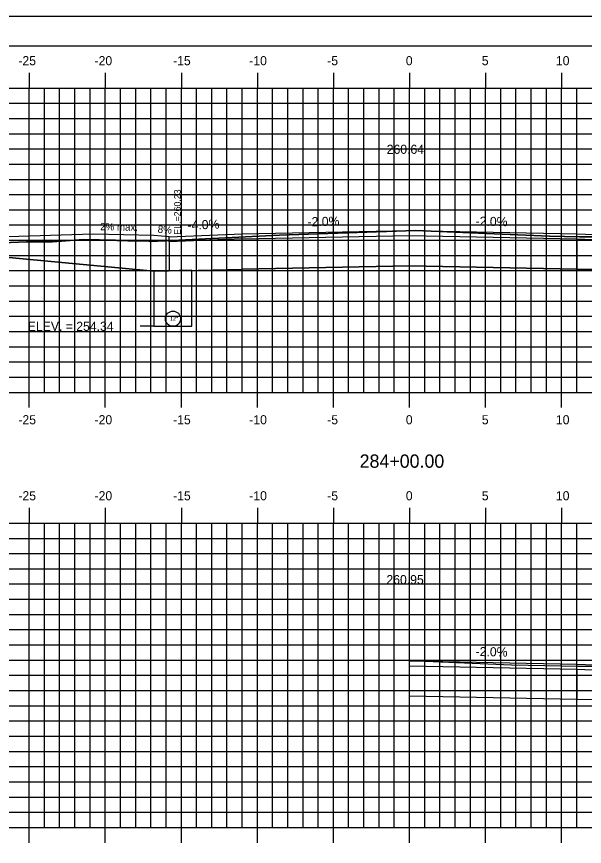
# Model space of a CAD drawing. Extents: x 856235 to 856405, y 366268 to 366378.
# Drawn here: x 856291.9 to 856329.3, y 366323.6 to 366378.2 of the extents above; entities that cross this region are included whole.
import ezdxf

# ---------------------------------------------------------------- set-up
doc = ezdxf.new("R2010")
doc.units = 0
for name, color, linetype in [('ANNOTATION', 7, 'Continuous'), ('BORDER', 7, 'Continuous'), ('D_Roadway_Centerline', 7, 'Continuous'), ('D_Roadway_Centerline_Text', 7, 'Continuous'), ('D_Roadway_Drive_Gravel_LT', 7, 'Continuous'), ('D_Roadway_Drive_SubGrade', 7, 'Continuous'), ('D_Roadway_Edge_Shoulder', 7, 'Continuous'), ('D_Roadway_SubGrade', 7, 'Continuous'), ('D_Text_Standard', 7, 'Continuous'), ('H_V ANNOTATION', 7, 'Continuous'), ('JUNK COM EXC', 7, 'Continuous'), ('junk strct exc', 7, 'Continuous'), ('MAJOR', 7, 'Continuous'), ('MINOR', 7, 'Continuous'), ('PDRAIN', 7, 'Continuous'), ('PLOT BOUNDARY', 7, 'Continuous'), ('S_Roadway_Centerline', 7, 'Continuous')]:
    doc.layers.add(name, color=color, linetype=linetype)

msp = doc.modelspace()

# ---------------------------------------------------------------- linework, layer by layer
at = {"layer": 'BORDER'}
msp.add_line((856402.781, 366376.236), (856242.781, 366376.236), dxfattribs=at)
at = {"layer": 'D_Roadway_Centerline'}
msp.add_lwpolyline([(856306.781, 366363.904), (856317.781, 366364.124), (856328.781, 366363.904)], dxfattribs=at)
at = {"layer": 'D_Roadway_Drive_Gravel_LT'}
for p, q in [((856296.981, 366363.872), (856265.781, 366362.934)), ((856300.981, 366363.792), (856296.981, 366363.872)), ((856301.981, 366363.712), (856300.981, 366363.792)), ((856301.981, 366363.379), (856301.981, 366363.712))]:
    msp.add_line(p, q, dxfattribs=at)
at = {"layer": 'D_Roadway_Drive_SubGrade'}
for p, q in [((856300.981, 366361.439), (856290.981, 366362.395)), ((856301.981, 366361.459), (856300.981, 366361.439))]:
    msp.add_line(p, q, dxfattribs=at)
at = {"layer": 'D_Roadway_Edge_Shoulder'}
for points in [[(856301.981, 366363.712), (856306.781, 366363.904), (856317.781, 366364.124), (856328.781, 366363.904), (856336.78, 366363.585)], [(856317.781, 366335.84), (856328.781, 366335.62), (856336.78, 366335.3)]]:
    msp.add_lwpolyline(points, dxfattribs=at)
at = {"layer": 'D_Roadway_SubGrade'}
for p, q in [((856317.781, 366335.506), (856328.781, 366335.286)), ((856328.781, 366335.286), (856328.781, 366333.286)), ((856328.781, 366333.286), (856317.781, 366333.506))]:
    msp.add_line(p, q, dxfattribs=at)
for points in [[(856306.781, 366361.571), (856306.781, 366363.571), (856317.781, 366363.791), (856328.781, 366363.571), (856328.781, 366361.571), (856317.781, 366361.791)], [(856306.781, 366363.571), (856301.981, 366363.379), (856301.981, 366361.475), (856306.781, 366361.571)]]:
    msp.add_lwpolyline(points, close=True, dxfattribs=at)
for points in [[(856336.781, 366361.411), (856328.781, 366361.571), (856328.781, 366363.571), (856336.781, 366363.251)], [(856336.781, 366333.126), (856328.781, 366333.286), (856328.781, 366335.286), (856336.781, 366334.966)]]:
    msp.add_lwpolyline(points, dxfattribs=at)
at = {"layer": 'D_Text_Standard'}
msp.add_lwpolyline([(856300.981, 366357.821), (856300.764, 366357.821), (856300.084, 366357.821)], dxfattribs=at)
at = {"layer": 'JUNK COM EXC'}
for points in [[(856346.125, 366365.758), (856337.467, 366365.5), (856335.581, 366364.715), (856334.342, 366364.246), (856334.308, 366364.232), (856333.97, 366363.951), (856333.914, 366363.825), (856333.689, 366363.627), (856329.863, 366363.704), (856328.954, 366363.708), (856326.986, 366363.743), (856318.175, 366364.117), (856309.225, 366363.802), (856307.438, 366363.733), (856301.74, 366363.432), (856300.981, 366363.404)], [(856300.981, 366363.404), (856300.702, 366363.394), (856300.563, 366363.43), (856296.348, 366363.536), (856294.317, 366363.378), (856292.601, 366363.365), (856286.23, 366363.117), (856265.781, 366362.934), (856265.781, 366361.768), (856290.981, 366362.395), (856300.981, 366361.439), (856306.781, 366361.571), (856317.781, 366361.791), (856328.781, 366361.571), (856337.781, 366361.391), (856337.781, 366364.18), (856340.197, 366364.228), (856343.261, 366365.249)]]:
    msp.add_lwpolyline(points, dxfattribs=at)
at = {"layer": 'junk strct exc'}
msp.add_lwpolyline([(856300.981, 366361.439), (856300.981, 366357.821), (856303.481, 366357.821), (856303.481, 366361.505)], close=True, dxfattribs=at)
at = {"layer": 'MAJOR'}
for p, q in [((856292.781, 366374.483), (856292.781, 366373.481)), ((856297.781, 366374.483), (856297.781, 366373.481)), ((856302.781, 366374.483), (856302.781, 366373.481)), ((856307.781, 366374.483), (856307.781, 366373.481)), ((856312.781, 366374.483), (856312.781, 366373.481)), ((856317.781, 366374.483), (856317.781, 366373.481)), ((856322.781, 366374.483), (856322.781, 366373.481)), ((856327.781, 366374.483), (856327.781, 366373.481)), ((856247.781, 366373.481), (856387.781, 366373.481)), ((856247.781, 366373.481), (856387.781, 366373.481)), ((856292.781, 366353.481), (856292.781, 366373.481)), ((856297.781, 366353.481), (856297.781, 366373.481)), ((856302.781, 366353.481), (856302.781, 366373.481)), ((856307.781, 366353.481), (856307.781, 366373.481)), ((856312.781, 366353.481), (856312.781, 366373.481)), ((856317.781, 366353.481), (856317.781, 366373.481)), ((856322.781, 366353.481), (856322.781, 366373.481)), ((856327.781, 366353.481), (856327.781, 366373.481)), ((856247.781, 366368.481), (856387.781, 366368.481)), ((856247.781, 366363.481), (856387.781, 366363.481)), ((856247.781, 366358.481), (856387.781, 366358.481)), ((856247.781, 366353.481), (856387.781, 366353.481)), ((856247.781, 366353.481), (856387.781, 366353.481)), ((856292.781, 366352.479), (856292.781, 366353.481)), ((856297.781, 366352.479), (856297.781, 366353.481)), ((856302.781, 366352.479), (856302.781, 366353.481)), ((856307.781, 366352.479), (856307.781, 366353.481)), ((856312.781, 366352.479), (856312.781, 366353.481)), ((856317.781, 366352.479), (856317.781, 366353.481)), ((856322.781, 366352.479), (856322.781, 366353.481)), ((856327.781, 366352.479), (856327.781, 366353.481)), ((856292.781, 366345.887), (856292.781, 366344.885)), ((856297.781, 366345.887), (856297.781, 366344.885)), ((856302.781, 366345.887), (856302.781, 366344.885)), ((856307.781, 366345.887), (856307.781, 366344.885)), ((856312.781, 366345.887), (856312.781, 366344.885)), ((856317.781, 366345.887), (856317.781, 366344.885)), ((856322.781, 366345.887), (856322.781, 366344.885)), ((856327.781, 366345.887), (856327.781, 366344.885)), ((856247.781, 366344.885), (856387.781, 366344.885)), ((856247.781, 366344.885), (856387.781, 366344.885)), ((856292.781, 366324.885), (856292.781, 366344.885)), ((856297.781, 366324.885), (856297.781, 366344.885)), ((856302.781, 366324.885), (856302.781, 366344.885)), ((856307.781, 366324.885), (856307.781, 366344.885)), ((856312.781, 366324.885), (856312.781, 366344.885)), ((856317.781, 366324.885), (856317.781, 366344.885)), ((856322.781, 366324.885), (856322.781, 366344.885)), ((856327.781, 366324.885), (856327.781, 366344.885)), ((856247.781, 366339.885), (856387.781, 366339.885)), ((856247.781, 366334.885), (856387.781, 366334.885)), ((856247.781, 366329.885), (856387.781, 366329.885)), ((856247.781, 366324.885), (856387.781, 366324.885)), ((856247.781, 366324.885), (856387.781, 366324.885)), ((856292.781, 366323.883), (856292.781, 366324.885)), ((856297.781, 366323.883), (856297.781, 366324.885)), ((856302.781, 366323.883), (856302.781, 366324.885)), ((856307.781, 366323.883), (856307.781, 366324.885)), ((856312.781, 366323.883), (856312.781, 366324.885)), ((856317.781, 366323.883), (856317.781, 366324.885)), ((856322.781, 366323.883), (856322.781, 366324.885)), ((856327.781, 366323.883), (856327.781, 366324.885))]:
    msp.add_line(p, q, dxfattribs=at)
at = {"layer": 'MINOR'}
for p, q in [((856293.781, 366353.481), (856293.781, 366373.481)), ((856294.781, 366353.481), (856294.781, 366373.481)), ((856295.781, 366353.481), (856295.781, 366373.481)), ((856296.781, 366353.481), (856296.781, 366373.481)), ((856298.781, 366353.481), (856298.781, 366373.481)), ((856299.781, 366353.481), (856299.781, 366373.481)), ((856300.781, 366353.481), (856300.781, 366373.481)), ((856301.781, 366353.481), (856301.781, 366373.481)), ((856303.781, 366353.481), (856303.781, 366373.481)), ((856304.781, 366353.481), (856304.781, 366373.481)), ((856305.781, 366353.481), (856305.781, 366373.481)), ((856306.781, 366353.481), (856306.781, 366373.481)), ((856308.781, 366353.481), (856308.781, 366373.481)), ((856309.781, 366353.481), (856309.781, 366373.481)), ((856310.781, 366353.481), (856310.781, 366373.481)), ((856311.781, 366353.481), (856311.781, 366373.481)), ((856313.781, 366353.481), (856313.781, 366373.481)), ((856314.781, 366353.481), (856314.781, 366373.481)), ((856315.781, 366353.481), (856315.781, 366373.481)), ((856316.781, 366353.481), (856316.781, 366373.481)), ((856318.781, 366353.481), (856318.781, 366373.481)), ((856319.781, 366353.481), (856319.781, 366373.481)), ((856320.781, 366353.481), (856320.781, 366373.481)), ((856321.781, 366353.481), (856321.781, 366373.481)), ((856323.781, 366353.481), (856323.781, 366373.481)), ((856324.781, 366353.481), (856324.781, 366373.481)), ((856325.781, 366353.481), (856325.781, 366373.481)), ((856326.781, 366353.481), (856326.781, 366373.481)), ((856328.781, 366353.481), (856328.781, 366373.481)), ((856247.781, 366372.481), (856387.781, 366372.481)), ((856247.781, 366371.481), (856387.781, 366371.481)), ((856247.781, 366370.481), (856387.781, 366370.481)), ((856247.781, 366369.481), (856387.781, 366369.481)), ((856247.781, 366367.481), (856387.781, 366367.481)), ((856247.781, 366366.481), (856387.781, 366366.481)), ((856247.781, 366365.481), (856387.781, 366365.481)), ((856247.781, 366364.481), (856387.781, 366364.481)), ((856247.781, 366362.481), (856387.781, 366362.481)), ((856247.781, 366361.481), (856387.781, 366361.481)), ((856247.781, 366360.481), (856387.781, 366360.481)), ((856247.781, 366359.481), (856387.781, 366359.481)), ((856247.781, 366357.481), (856387.781, 366357.481)), ((856247.781, 366356.481), (856387.781, 366356.481)), ((856247.781, 366355.481), (856387.781, 366355.481)), ((856247.781, 366354.481), (856387.781, 366354.481)), ((856293.781, 366324.885), (856293.781, 366344.885)), ((856294.781, 366324.885), (856294.781, 366344.885)), ((856295.781, 366324.885), (856295.781, 366344.885)), ((856296.781, 366324.885), (856296.781, 366344.885)), ((856298.781, 366324.885), (856298.781, 366344.885)), ((856299.781, 366324.885), (856299.781, 366344.885)), ((856300.781, 366324.885), (856300.781, 366344.885)), ((856301.781, 366324.885), (856301.781, 366344.885)), ((856303.781, 366324.885), (856303.781, 366344.885)), ((856304.781, 366324.885), (856304.781, 366344.885)), ((856305.781, 366324.885), (856305.781, 366344.885)), ((856306.781, 366324.885), (856306.781, 366344.885)), ((856308.781, 366324.885), (856308.781, 366344.885)), ((856309.781, 366324.885), (856309.781, 366344.885)), ((856310.781, 366324.885), (856310.781, 366344.885)), ((856311.781, 366324.885), (856311.781, 366344.885)), ((856313.781, 366324.885), (856313.781, 366344.885)), ((856314.781, 366324.885), (856314.781, 366344.885)), ((856315.781, 366324.885), (856315.781, 366344.885)), ((856316.781, 366324.885), (856316.781, 366344.885)), ((856318.781, 366324.885), (856318.781, 366344.885)), ((856319.781, 366324.885), (856319.781, 366344.885)), ((856320.781, 366324.885), (856320.781, 366344.885)), ((856321.781, 366324.885), (856321.781, 366344.885)), ((856323.781, 366324.885), (856323.781, 366344.885)), ((856324.781, 366324.885), (856324.781, 366344.885)), ((856325.781, 366324.885), (856325.781, 366344.885)), ((856326.781, 366324.885), (856326.781, 366344.885)), ((856328.781, 366324.885), (856328.781, 366344.885)), ((856247.781, 366343.885), (856387.781, 366343.885)), ((856247.781, 366342.885), (856387.781, 366342.885)), ((856247.781, 366341.885), (856387.781, 366341.885)), ((856247.781, 366340.885), (856387.781, 366340.885)), ((856247.781, 366338.885), (856387.781, 366338.885)), ((856247.781, 366337.885), (856387.781, 366337.885)), ((856247.781, 366336.885), (856387.781, 366336.885)), ((856247.781, 366335.885), (856387.781, 366335.885)), ((856247.781, 366333.885), (856387.781, 366333.885)), ((856247.781, 366332.885), (856387.781, 366332.885)), ((856247.781, 366331.885), (856387.781, 366331.885)), ((856247.781, 366330.885), (856387.781, 366330.885)), ((856247.781, 366328.885), (856387.781, 366328.885)), ((856247.781, 366327.885), (856387.781, 366327.885)), ((856247.781, 366326.885), (856387.781, 366326.885)), ((856247.781, 366325.885), (856387.781, 366325.885))]:
    msp.add_line(p, q, dxfattribs=at)
at = {"layer": 'PDRAIN'}
msp.add_lwpolyline([(856300.981, 366361.439), (856300.981, 366357.821), (856303.481, 366357.821), (856303.481, 366361.505)], dxfattribs=at)
msp.add_circle((856302.231, 366358.321), 0.5, dxfattribs=at)
at = {"layer": 'PLOT BOUNDARY'}
msp.add_lwpolyline([(856234.688, 366268.177), (856404.688, 366268.177), (856404.688, 366378.177), (856234.688, 366378.177)], close=True, dxfattribs=at)
at = {"layer": 'S_Roadway_Centerline'}
for points in [[(856286.23, 366363.117), (856292.601, 366363.365), (856294.317, 366363.378), (856296.348, 366363.536), (856299.261, 366363.444), (856300.563, 366363.43), (856300.702, 366363.394), (856301.74, 366363.432), (856307.438, 366363.733), (856309.225, 366363.802), (856318.175, 366364.117), (856326.986, 366363.743), (856328.954, 366363.708), (856329.863, 366363.704)], [(856317.781, 366335.852), (856324.494, 366335.567), (856328.856, 366335.491), (856330.87, 366335.48), (856333.679, 366335.424), (856334.19, 366335.873), (856334.251, 366336.012), (856334.324, 366336.04), (856334.37, 366336.058), (856335.499, 366336.497), (856337.291, 366337.198), (856342.56, 366337.355), (856355.985, 366337.544), (856356.051, 366337.541), (856356.28, 366337.545), (856356.313, 366337.567), (856358.146, 366339.119), (856360.492, 366339.129), (856361.321, 366339.133), (856361.368, 366339.089), (856361.518, 366338.578)]]:
    msp.add_lwpolyline(points, dxfattribs=at)

# ---------------------------------------------------------------- texts
at = {"layer": 'ANNOTATION'}
for s, rotation, p in [('-2.0%', 1.1458, (856311.084, 366364.391)), ('-2.0%', 358.8542, (856322.124, 366364.438)), ('-4.0%', 2.2906, (856303.197, 366364.162)), ('-2.0%', 358.8542, (856322.124, 366336.153)), ('-2.0%', 358.8542, (856322.124, 366336.153))]:
    msp.add_text(s, height=0.6, rotation=rotation, dxfattribs=at).set_placement(p)
at = {"layer": 'D_Roadway_Centerline_Text'}
for s, p in [('260.64', (856316.282, 366369.156)), ('260.95', (856316.264, 366340.872))]:
    msp.add_text(s, height=0.6, dxfattribs=at).set_placement(p)
at = {"layer": 'D_Roadway_Drive_Gravel_LT'}
for s, rotation, p in [('2% max.', 358.8078, (856297.434, 366364.142)), ('8%', 355.4261, (856301.211, 366363.979))]:
    msp.add_text(s, height=0.48, rotation=rotation, dxfattribs=at).set_placement(p)
at = {"layer": 'D_Text_Standard'}
msp.add_text(' EL.=260.23', height=0.4335, rotation=90, dxfattribs=at).set_placement((856302.738, 366363.678))
msp.add_text('ELEV. = 254.34', height=0.6, dxfattribs=at).set_placement((856292.684, 366357.521))
at = {"layer": 'H_V ANNOTATION'}
for s, height, p in [('-25', 0.6, (856292.066, 366374.981)), ('-20', 0.6, (856297.074, 366374.981)), ('-15', 0.6, (856302.238, 366374.981)), ('-10', 0.6, (856307.246, 366374.981)), ('-5', 0.6, (856312.371, 366374.981)), ('0', 0.6, (856317.54, 366374.981)), ('5', 0.6, (856322.532, 366374.981)), ('10', 0.6, (856327.406, 366374.981)), ('-25', 0.6, (856292.066, 366351.381)), ('-20', 0.6, (856297.074, 366351.381)), ('-15', 0.6, (856302.238, 366351.381)), ('-10', 0.6, (856307.246, 366351.381)), ('-5', 0.6, (856312.371, 366351.381)), ('0', 0.6, (856317.54, 366351.381)), ('5', 0.6, (856322.532, 366351.381)), ('10', 0.6, (856327.406, 366351.381)), ('284+00.00', 0.875, (856314.503, 366348.524)), ('-25', 0.6, (856292.066, 366346.385)), ('-20', 0.6, (856297.074, 366346.385)), ('-15', 0.6, (856302.238, 366346.385)), ('-10', 0.6, (856307.246, 366346.385)), ('-5', 0.6, (856312.371, 366346.385)), ('0', 0.6, (856317.54, 366346.385)), ('5', 0.6, (856322.532, 366346.385)), ('10', 0.6, (856327.406, 366346.385))]:
    msp.add_text(s, height=height, dxfattribs=at).set_placement(p)
at = {"layer": 'PDRAIN'}
msp.add_text('12"', height=0.25, dxfattribs=at).set_placement((856302.04, 366358.197))
at = {"layer": 'S_Roadway_Centerline'}
for s, p in [('C', (856318.17, 366364.117)), ('L', (856318.175, 366364.109)), ('C', (856318.045, 366335.841)), ('L', (856318.05, 366335.834))]:
    msp.add_text(s, height=0.0146, dxfattribs=at).set_placement(p)

doc.saveas('drawing.dxf')
